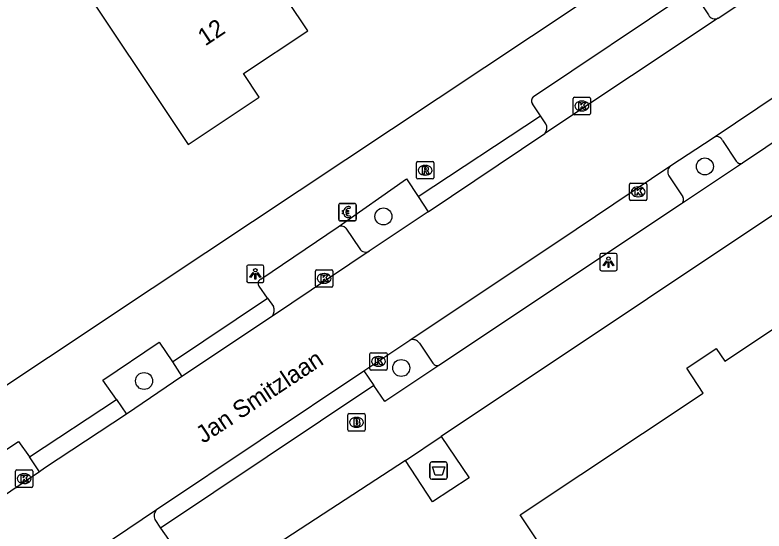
# Model space of a CAD drawing. Extents: x 161354 to 161876, y 382161 to 382804.
# Drawn here: x 161566.47 to 161609.6, y 382598.71 to 382628.43 of the extents above; entities that cross this region are included whole.
import ezdxf

# ---------------------------------------------------------------- set-up
doc = ezdxf.new("R2010")
doc.units = 0
for name, color, linetype in [('IMGEO_Afval_apart_plaats', 7, 'Continuous'), ('IMGEO_Betaalautomaat', 7, 'Continuous'), ('IMGEO_Boom', 7, 'Continuous'), ('IMGEO_Brandkraan', 7, 'Continuous'), ('IMGEO_Kolk', 7, 'Continuous'), ('IMGEO_Lichtpunt', 7, 'Continuous'), ('IMGEO_Openbare_ruimte_label', 7, 'Continuous'), ('IMGEO_Pand', 7, 'Continuous'), ('IMGEO_Pand_nummerreeks', 7, 'Continuous'), ('IMGEO_Parkeervlak_open', 7, 'Continuous'), ('IMGEO_Rijbaan_lokaal_open', 7, 'Continuous'), ('IMGEO_Rioolput', 7, 'Continuous'), ('IMGEO_Voetpad_gesloten', 7, 'Continuous'), ('IMGEO_Voetpad_open', 7, 'Continuous')]:
    doc.layers.add(name, color=color, linetype=linetype)

msp = doc.modelspace()

# ---------------------------------------------------------------- linework, layer by layer
at = {"layer": 'IMGEO_Afval_apart_plaats'}
for p, q in [((161590.37, 382601.787), (161590.37, 382602.587)), ((161590.37, 382602.587), (161590.37, 382601.787)), ((161590.47, 382602.687), (161591.26, 382602.687)), ((161591.26, 382602.687), (161590.47, 382602.687)), ((161591.36, 382602.587), (161591.36, 382601.787)), ((161591.36, 382601.787), (161591.36, 382602.587)), ((161591.26, 382601.687), (161590.47, 382601.687)), ((161590.47, 382601.687), (161591.26, 382601.687))]:
    msp.add_line(p, q, dxfattribs=at)
msp.add_lwpolyline([(161590.513, 382602.401), (161591.217, 382602.401), (161591.068, 382601.931), (161590.662, 382601.931), (161590.513, 382602.401)], dxfattribs=at)
for centre, start, end in [((161590.47, 382602.587), 90, 180), ((161590.47, 382602.587), 90, 180), ((161591.26, 382602.587), 0, 90), ((161591.26, 382602.587), 360, 90), ((161590.47, 382601.787), 180, 270), ((161590.47, 382601.787), 180, 270), ((161591.26, 382601.787), 270, 0), ((161591.26, 382601.787), 270, 0)]:
    msp.add_arc(centre, 0.1, start, end, dxfattribs=at)
at = {"layer": 'IMGEO_Betaalautomaat'}
for p, q in [((161585.189, 382617.577), (161586.03, 382617.577)), ((161586.03, 382617.577), (161585.189, 382617.577)), ((161585.114, 382616.653), (161585.114, 382617.494)), ((161585.114, 382617.494), (161585.114, 382616.653)), ((161585.397, 382617.041), (161585.397, 382617.109)), ((161585.518, 382617.109), (161585.518, 382617.041)), ((161585.776, 382617.382), (161585.759, 382617.282)), ((161586.113, 382617.503), (161586.113, 382616.662)), ((161586.113, 382616.662), (161586.113, 382617.503)), ((161585.763, 382616.876), (161585.785, 382616.789)), ((161586.039, 382616.578), (161585.198, 382616.578)), ((161585.198, 382616.578), (161586.039, 382616.578))]:
    msp.add_line(p, q, dxfattribs=at)
for points in [[(161585.397, 382617.109), (161585.328, 382617.109), (161585.328, 382617.178), (161585.407, 382617.178)], [(161585.529, 382617.178), (161585.676, 382617.178), (161585.676, 382617.109), (161585.518, 382617.109)], [(161585.402, 382616.972), (161585.328, 382616.972), (161585.328, 382617.041), (161585.397, 382617.041)], [(161585.518, 382617.041), (161585.676, 382617.041), (161585.676, 382616.972), (161585.532, 382616.972)]]:
    msp.add_lwpolyline(points, dxfattribs=at)
for centre, radius, start, end in [((161585.192, 382617.5), 0.0779, 92.4484, 184.2845), ((161585.192, 382617.5), 0.0779, 92.4484, 184.2845), ((161586.036, 382617.5), 0.0779, 2.4484, 94.2845), ((161586.036, 382617.5), 0.0779, 2.4484, 94.2845), ((161585.69, 382617.102), 0.293, 73.014, 165.0139), ((161585.696, 382617.115), 0.179, 69.3236, 159.5683), ((161585.192, 382616.656), 0.0779, 182.4484, 274.2845), ((161585.192, 382616.656), 0.0779, 182.4484, 274.2845), ((161585.663, 382617.027), 0.267, 191.8096, 297.0389), ((161585.696, 382617.042), 0.179, 202.7625, 291.8693), ((161586.036, 382616.656), 0.0779, 272.4484, 4.2845), ((161586.036, 382616.656), 0.0779, 272.4484, 4.2845)]:
    msp.add_arc(centre, radius, start, end, dxfattribs=at)
at = {"layer": 'IMGEO_Boom'}
for centre in [(161606.198, 382619.709), (161587.688, 382616.829), (161588.717, 382608.1), (161573.904, 382607.351)]:
    msp.add_circle(centre, 0.489, dxfattribs=at)
at = {"layer": 'IMGEO_Brandkraan'}
for p, q in [((161585.712, 382605.47), (161586.564, 382605.47)), ((161585.637, 382604.544), (161585.637, 382605.396)), ((161586.125, 382605.25), (161586.15, 382605.25)), ((161586.638, 382605.396), (161586.638, 382604.544)), ((161586.148, 382604.69), (161586.123, 382604.69)), ((161586.564, 382604.47), (161585.712, 382604.47))]:
    msp.add_line(p, q, dxfattribs=at)
for points in [[(161585.712, 382605.47), (161586.564, 382605.47)], [(161585.637, 382604.544), (161585.637, 382605.396)], [(161585.985, 382605.17), (161585.985, 382604.77), (161586.198, 382604.77)], [(161586.216, 382605.17), (161585.985, 382605.17)], [(161586.164, 382605.089), (161586.11, 382605.089), (161586.11, 382605.013)], [(161586.11, 382605.013), (161586.163, 382605.013)], [(161586.638, 382605.396), (161586.638, 382604.544)], [(161586.172, 382604.937), (161586.11, 382604.937), (161586.11, 382604.856)], [(161586.11, 382604.856), (161586.172, 382604.856)], [(161586.564, 382604.47), (161585.712, 382604.47)]]:
    msp.add_lwpolyline(points, dxfattribs=at)
for centre, radius, start, end in [((161585.714, 382605.394), 0.0765, 91.552, 178.448), ((161585.714, 382605.394), 0.0765, 91.552, 178.448), ((161586.562, 382605.394), 0.0765, 1.552, 88.448), ((161586.562, 382605.394), 0.0765, 1.552, 88.448), ((161586.165, 382605.051), 0.0379, 267.8285, 90.9355), ((161586.22, 382605.025), 0.145, 59.4692, 91.5367), ((161586.245, 382605.072), 0.0922, 285.5137, 58.1501), ((161586.173, 382604.896), 0.0404, 269.8759, 90.5077), ((161586.204, 382605.021), 0.251, 268.6676, 293.5347), ((161586.25, 382604.88), 0.105, 301.3115, 78.989), ((161585.714, 382604.546), 0.0765, 181.552, 268.448), ((161585.714, 382604.546), 0.0765, 181.552, 268.448), ((161586.562, 382604.546), 0.0765, 271.552, 358.448), ((161586.562, 382604.546), 0.0765, 271.552, 358.448)]:
    msp.add_arc(centre, radius, start, end, dxfattribs=at)
for centre, major_axis, ratio, start_param, end_param in [((161586.124, 382604.97), (-0.387, 0.002), 0.722429, 4.712389, 7.853982), ((161586.149, 382604.97), (-0.39, 0.002), 0.717154, 1.570796, 4.712389)]:
    msp.add_ellipse(centre, major_axis=major_axis, ratio=ratio, start_param=start_param, end_param=end_param, dxfattribs=at)
at = {"layer": 'IMGEO_Kolk'}
for p, q in [((161598.619, 382622.763), (161598.619, 382623.615)), ((161598.694, 382623.689), (161599.546, 382623.689)), ((161599.62, 382623.615), (161599.62, 382622.763)), ((161599.107, 382623.469), (161599.132, 382623.469)), ((161599.546, 382622.689), (161598.694, 382622.689)), ((161599.13, 382622.909), (161599.105, 382622.909)), ((161601.855, 382617.819), (161601.855, 382618.671)), ((161601.93, 382618.745), (161602.782, 382618.745)), ((161602.343, 382618.525), (161602.368, 382618.525)), ((161602.856, 382618.671), (161602.856, 382617.819)), ((161602.366, 382617.965), (161602.341, 382617.965)), ((161602.782, 382617.745), (161601.93, 382617.745)), ((161583.78, 382612.832), (161583.78, 382613.684)), ((161583.855, 382613.758), (161584.707, 382613.758)), ((161584.781, 382613.684), (161584.781, 382612.832)), ((161584.268, 382613.538), (161584.293, 382613.538)), ((161584.291, 382612.978), (161584.266, 382612.978)), ((161584.707, 382612.758), (161583.855, 382612.758)), ((161586.903, 382608.055), (161586.903, 382608.907)), ((161586.978, 382608.981), (161587.83, 382608.981)), ((161587.904, 382608.907), (161587.904, 382608.055)), ((161587.391, 382608.761), (161587.416, 382608.761)), ((161587.414, 382608.201), (161587.389, 382608.201)), ((161587.83, 382607.981), (161586.978, 382607.981)), ((161566.5, 382601.3), (161566.5, 382602.152)), ((161566.575, 382602.226), (161567.427, 382602.226)), ((161566.988, 382602.006), (161567.013, 382602.006)), ((161567.501, 382602.152), (161567.501, 382601.3)), ((161567.427, 382601.226), (161566.575, 382601.226)), ((161567.011, 382601.446), (161566.986, 382601.446))]:
    msp.add_line(p, q, dxfattribs=at)
for points in [[(161598.619, 382622.763), (161598.619, 382623.615)], [(161598.694, 382623.689), (161599.546, 382623.689)], [(161599.62, 382623.615), (161599.62, 382622.763)], [(161598.94, 382623.389), (161599.063, 382623.389), (161599.063, 382623.238), (161599.193, 382623.389), (161599.357, 382623.389), (161599.211, 382623.238), (161599.364, 382622.989), (161599.212, 382622.989), (161599.127, 382623.153), (161599.063, 382623.086), (161599.063, 382622.989), (161598.94, 382622.989), (161598.94, 382623.389)], [(161599.546, 382622.689), (161598.694, 382622.689)], [(161601.855, 382617.819), (161601.855, 382618.671)], [(161601.93, 382618.745), (161602.782, 382618.745)], [(161602.176, 382618.445), (161602.299, 382618.445), (161602.299, 382618.294), (161602.429, 382618.445), (161602.593, 382618.445), (161602.447, 382618.294), (161602.6, 382618.045), (161602.448, 382618.045), (161602.363, 382618.209), (161602.299, 382618.142), (161602.299, 382618.045), (161602.176, 382618.045), (161602.176, 382618.445)], [(161602.856, 382618.671), (161602.856, 382617.819)], [(161602.782, 382617.745), (161601.93, 382617.745)], [(161583.78, 382612.832), (161583.78, 382613.684)], [(161583.855, 382613.758), (161584.707, 382613.758)], [(161584.781, 382613.684), (161584.781, 382612.832)], [(161584.101, 382613.458), (161584.224, 382613.458), (161584.224, 382613.307), (161584.354, 382613.458), (161584.518, 382613.458), (161584.372, 382613.307), (161584.525, 382613.058), (161584.373, 382613.058), (161584.288, 382613.222), (161584.224, 382613.155), (161584.224, 382613.058), (161584.101, 382613.058), (161584.101, 382613.458)], [(161584.707, 382612.758), (161583.855, 382612.758)], [(161586.903, 382608.055), (161586.903, 382608.907)], [(161586.978, 382608.981), (161587.83, 382608.981)], [(161587.904, 382608.907), (161587.904, 382608.055)], [(161587.224, 382608.681), (161587.347, 382608.681), (161587.347, 382608.53), (161587.477, 382608.681), (161587.641, 382608.681), (161587.495, 382608.53), (161587.648, 382608.281), (161587.496, 382608.281), (161587.411, 382608.445), (161587.347, 382608.378), (161587.347, 382608.281), (161587.224, 382608.281), (161587.224, 382608.681)], [(161587.83, 382607.981), (161586.978, 382607.981)], [(161566.5, 382601.3), (161566.5, 382602.152)], [(161566.575, 382602.226), (161567.427, 382602.226)], [(161567.501, 382602.152), (161567.501, 382601.3)], [(161566.821, 382601.926), (161566.944, 382601.926), (161566.944, 382601.775), (161567.074, 382601.926), (161567.238, 382601.926), (161567.092, 382601.775), (161567.245, 382601.526), (161567.093, 382601.526), (161567.008, 382601.69), (161566.944, 382601.623), (161566.944, 382601.526), (161566.821, 382601.526), (161566.821, 382601.926)], [(161567.427, 382601.226), (161566.575, 382601.226)]]:
    msp.add_lwpolyline(points, dxfattribs=at)
for centre, start, end in [((161598.696, 382623.613), 91.552, 178.448), ((161598.696, 382623.613), 91.552, 178.448), ((161599.544, 382623.613), 1.552, 88.448), ((161599.544, 382623.613), 1.552, 88.448), ((161598.696, 382622.765), 181.552, 268.448), ((161598.696, 382622.765), 181.552, 268.448), ((161599.544, 382622.765), 271.552, 358.448), ((161599.544, 382622.765), 271.552, 358.448), ((161601.932, 382618.669), 91.552, 178.448), ((161601.932, 382618.669), 91.552, 178.448), ((161602.78, 382618.669), 1.552, 88.448), ((161602.78, 382618.669), 1.552, 88.448), ((161601.932, 382617.821), 181.552, 268.448), ((161601.932, 382617.821), 181.552, 268.448), ((161602.78, 382617.821), 271.552, 358.448), ((161602.78, 382617.821), 271.552, 358.448), ((161583.857, 382613.682), 91.552, 178.448), ((161583.857, 382613.682), 91.552, 178.448), ((161584.705, 382613.682), 1.552, 88.448), ((161584.705, 382613.682), 1.552, 88.448), ((161583.857, 382612.834), 181.552, 268.448), ((161583.857, 382612.834), 181.552, 268.448), ((161584.705, 382612.834), 271.552, 358.448), ((161584.705, 382612.834), 271.552, 358.448), ((161586.98, 382608.905), 91.552, 178.448), ((161586.98, 382608.905), 91.552, 178.448), ((161587.828, 382608.905), 1.552, 88.448), ((161587.828, 382608.905), 1.552, 88.448), ((161586.98, 382608.057), 181.552, 268.448), ((161586.98, 382608.057), 181.552, 268.448), ((161587.828, 382608.057), 271.552, 358.448), ((161587.828, 382608.057), 271.552, 358.448), ((161566.577, 382602.15), 91.552, 178.448), ((161566.577, 382602.15), 91.552, 178.448), ((161567.425, 382602.15), 1.552, 88.448), ((161567.425, 382602.15), 1.552, 88.448), ((161566.577, 382601.302), 181.552, 268.448), ((161566.577, 382601.302), 181.552, 268.448), ((161567.425, 382601.302), 271.552, 358.448), ((161567.425, 382601.302), 271.552, 358.448)]:
    msp.add_arc(centre, 0.0765, start, end, dxfattribs=at)
for centre, major_axis, ratio, start_param, end_param in [((161599.106, 382623.189), (-0.387, 0.002), 0.722429, 4.712389, 7.853982), ((161599.131, 382623.189), (-0.39, 0.002), 0.717154, 1.570796, 4.712389), ((161602.342, 382618.245), (-0.387, 0.002), 0.722429, 4.712389, 7.853982), ((161602.367, 382618.245), (-0.39, 0.002), 0.717154, 1.570796, 4.712389), ((161584.267, 382613.258), (-0.387, 0.002), 0.722429, 4.712389, 7.853982), ((161584.292, 382613.258), (-0.39, 0.002), 0.717154, 1.570796, 4.712389), ((161587.39, 382608.481), (-0.387, 0.002), 0.722429, 4.712389, 7.853982), ((161587.415, 382608.481), (-0.39, 0.002), 0.717154, 1.570796, 4.712389), ((161566.987, 382601.726), (-0.387, 0.002), 0.722429, 4.712389, 7.853982), ((161567.012, 382601.726), (-0.39, 0.002), 0.717154, 1.570796, 4.712389)]:
    msp.add_ellipse(centre, major_axis=major_axis, ratio=ratio, start_param=start_param, end_param=end_param, dxfattribs=at)
at = {"layer": 'IMGEO_Lichtpunt'}
for p, q in [((161600.151, 382614.603), (161600.151, 382613.796)), ((161600.151, 382614.603), (161600.151, 382613.796)), ((161601.053, 382614.698), (161600.245, 382614.698)), ((161601.053, 382614.698), (161600.245, 382614.698)), ((161601.147, 382613.796), (161601.147, 382614.603)), ((161601.147, 382613.796), (161601.147, 382614.603)), ((161579.814, 382613.93), (161579.814, 382613.123)), ((161579.814, 382613.93), (161579.814, 382613.123)), ((161580.716, 382614.025), (161579.908, 382614.025)), ((161580.716, 382614.025), (161579.908, 382614.025)), ((161580.81, 382613.123), (161580.81, 382613.93)), ((161580.81, 382613.123), (161580.81, 382613.93)), ((161600.245, 382613.702), (161601.053, 382613.702)), ((161600.245, 382613.702), (161601.053, 382613.702)), ((161579.908, 382613.029), (161580.716, 382613.029)), ((161579.908, 382613.029), (161580.716, 382613.029))]:
    msp.add_line(p, q, dxfattribs=at)
for points in [[(161600.525, 382614.267), (161600.564, 382614.239), (161600.376, 382613.977), (161600.338, 382614.004), (161600.525, 382614.267)], [(161600.627, 382614.219), (161600.674, 382614.219), (161600.674, 382613.897), (161600.627, 382613.897), (161600.627, 382614.219)], [(161600.737, 382614.239), (161600.775, 382614.266), (161600.962, 382614.004), (161600.923, 382613.976), (161600.737, 382614.239)], [(161580.188, 382613.594), (161580.227, 382613.566), (161580.039, 382613.304), (161580.001, 382613.331), (161580.188, 382613.594)], [(161580.29, 382613.546), (161580.337, 382613.546), (161580.337, 382613.224), (161580.29, 382613.224), (161580.29, 382613.546)], [(161580.4, 382613.566), (161580.438, 382613.593), (161580.625, 382613.331), (161580.586, 382613.303), (161580.4, 382613.566)]]:
    msp.add_lwpolyline(points, dxfattribs=at)
for centre in [(161600.65, 382614.401), (161580.313, 382613.728)]:
    msp.add_circle(centre, 0.0994, dxfattribs=at)
for centre, start, end in [((161600.245, 382614.603), 90, 180), ((161600.245, 382614.603), 90, 180), ((161601.053, 382614.603), 0, 90), ((161601.053, 382614.603), 0, 90), ((161579.908, 382613.93), 90, 180), ((161579.908, 382613.93), 90, 180), ((161580.716, 382613.93), 0, 90), ((161580.716, 382613.93), 0, 90), ((161600.245, 382613.796), 180, 270), ((161600.245, 382613.796), 180, 270), ((161601.053, 382613.796), 270, 0), ((161601.053, 382613.796), 270, 360), ((161579.908, 382613.123), 180, 270), ((161579.908, 382613.123), 180, 270), ((161580.716, 382613.123), 270, 0), ((161580.716, 382613.123), 270, 360)]:
    msp.add_arc(centre, 0.0946, start, end, dxfattribs=at)
at = {"layer": 'IMGEO_Pand'}
for points in [[(161565.599, 382634.459), (161568.37, 382630.297), (161569.66, 382631.156), (161576.439, 382620.977), (161580.533, 382623.704), (161579.633, 382625.056), (161583.334, 382627.521), (161580.992, 382631.038), (161582.16, 382631.816), (161579.388, 382635.978), (161576.632, 382640.114), (161575.975, 382639.677), (161575.266, 382640.743), (161575.924, 382641.181), (161573.679, 382644.552), (161575.985, 382646.088), (161572.304, 382651.615), (161565.14, 382646.843), (161570.96, 382638.104), (161569.803, 382637.333), (161569.021, 382638.506), (161566.041, 382636.521), (161566.822, 382635.347), (161565.599, 382634.459)], [(161609.323, 382577.814), (161601.467, 382589.619), (161598.697, 382593.782), (161599.229, 382594.136), (161595.569, 382599.636), (161606.108, 382606.65), (161605.154, 382608.083), (161606.858, 382609.217), (161607.344, 382608.485), (161625.993, 382620.895)]]:
    msp.add_lwpolyline(points, dxfattribs=at)
at = {"layer": 'IMGEO_Parkeervlak_open'}
for points in [[(161605.625, 382629.631), (161606.407, 382628.432)], [(161607.212, 382621.21), (161608.007, 382620.009)], [(161604.13, 382619.174), (161604.931, 382617.96)], [(161585.528, 382616.145), (161586.327, 382614.968)], [(161589.758, 382609.534), (161590.54, 382608.383)]]:
    msp.add_lwpolyline(points, dxfattribs=at)
for centre, radius, start, end in [((161606.767, 382628.608), 0.401, 205.9885, 298.6427), ((161606.878, 382621.057), 0.368, 24.6315, 123.0538), ((161604.529, 382619.407), 0.462, 129.6828, 210.2901), ((161608.241, 382620.144), 0.27, 210.0365, 297.6516), ((161604.653, 382617.795), 0.323, 309.9997, 30.7608), ((161585.25, 382615.898), 0.371, 41.6099, 117.1043), ((161586.677, 382615.189), 0.414, 212.2674, 298.9748), ((161589.39, 382609.291), 0.441, 33.4839, 113.1759), ((161590.789, 382608.525), 0.287, 209.7009, 300.5265)]:
    msp.add_arc(centre, radius, start, end, dxfattribs=at)
at = {"layer": 'IMGEO_Rijbaan_lokaal_open'}
for points in [[(161606.959, 382628.256), (161609.534, 382629.982)], [(161606.677, 382621.365), (161617.031, 382628.308)], [(161606.959, 382628.256), (161596.988, 382621.601)], [(161590.272, 382617.093), (161596.988, 382621.601)], [(161604.234, 382619.763), (161606.677, 382621.365)], [(161589.217, 382609.696), (161598.787, 382616.092), (161604.234, 382619.763)], [(161590.272, 382617.093), (161586.877, 382614.827)], [(161586.877, 382614.827), (161581.294, 382611.082)], [(161581.294, 382611.082), (161576.086, 382607.606)], [(161586.553, 382607.94), (161589.217, 382609.696)], [(161576.086, 382607.606), (161572.895, 382605.439)], [(161574.626, 382599.941), (161586.553, 382607.94)], [(161572.895, 382605.439), (161568.174, 382602.328), (161567.876, 382602.127)], [(161567.876, 382602.127), (161562.92, 382598.78)], [(161568.848, 382596.061), (161574.626, 382599.941)]]:
    msp.add_lwpolyline(points, dxfattribs=at)
at = {"layer": 'IMGEO_Rioolput'}
for p, q in [((161589.592, 382619.06), (161589.592, 382619.912)), ((161589.667, 382619.986), (161590.519, 382619.986)), ((161590.08, 382619.766), (161590.105, 382619.766)), ((161590.593, 382619.912), (161590.593, 382619.06)), ((161590.519, 382618.986), (161589.667, 382618.986)), ((161590.103, 382619.206), (161590.078, 382619.206))]:
    msp.add_line(p, q, dxfattribs=at)
for points in [[(161589.592, 382619.06), (161589.592, 382619.912)], [(161589.667, 382619.986), (161590.519, 382619.986)], [(161590.181, 382619.684), (161589.929, 382619.686), (161589.929, 382619.286)], [(161590.593, 382619.912), (161590.593, 382619.06)], [(161589.929, 382619.286), (161590.053, 382619.286), (161590.053, 382619.448), (161590.064, 382619.448)], [(161590.107, 382619.605), (161590.053, 382619.605), (161590.053, 382619.524)], [(161590.053, 382619.524), (161590.105, 382619.524)], [(161590.111, 382619.419), (161590.182, 382619.286), (161590.322, 382619.286), (161590.257, 382619.412)], [(161590.519, 382618.986), (161589.667, 382618.986)]]:
    msp.add_lwpolyline(points, dxfattribs=at)
for centre, radius, start, end in [((161589.669, 382619.91), 0.0765, 91.552, 178.448), ((161589.669, 382619.91), 0.0765, 91.552, 178.448), ((161590.18, 382619.574), 0.109, 350.3612, 89.416), ((161590.517, 382619.91), 0.0765, 1.552, 88.448), ((161590.517, 382619.91), 0.0765, 1.552, 88.448), ((161590.063, 382619.395), 0.0533, 26.0293, 88.6989), ((161590.089, 382619.713), 0.19, 274.7715, 282.9687), ((161590.113, 382619.509), 0.0964, 77.0061, 93.1865), ((161590.127, 382619.566), 0.0378, 276.6634, 79.6772), ((161590.178, 382619.574), 0.112, 277.5842, 350.9817), ((161590.162, 382619.359), 0.108, 29.5134, 73.7905), ((161589.669, 382619.062), 0.0765, 181.552, 268.448), ((161589.669, 382619.062), 0.0765, 181.552, 268.448), ((161590.517, 382619.062), 0.0765, 271.552, 358.448), ((161590.517, 382619.062), 0.0765, 271.552, 358.448)]:
    msp.add_arc(centre, radius, start, end, dxfattribs=at)
for centre, major_axis, ratio, start_param, end_param in [((161590.079, 382619.486), (-0.387, 0.002), 0.722429, 4.712389, 7.853982), ((161590.104, 382619.486), (-0.39, 0.002), 0.717154, 1.570796, 4.712389)]:
    msp.add_ellipse(centre, major_axis=major_axis, ratio=ratio, start_param=start_param, end_param=end_param, dxfattribs=at)
at = {"layer": 'IMGEO_Voetpad_gesloten'}
for points in [[(161591.014, 382604.147), (161592.626, 382601.772), (161590.519, 382600.398), (161588.954, 382602.772)], [(161588.954, 382602.772), (161591.014, 382604.147)]]:
    msp.add_lwpolyline(points, dxfattribs=at)
at = {"layer": 'IMGEO_Voetpad_open'}
for points in [[(161628.452, 382648.518), (161612.356, 382637.679), (161612.276, 382637.879), (161577.471, 382614.736), (161574.373, 382612.676), (161556.508, 382600.797), (161530.719, 382583.477), (161519.986, 382585.99)], [(161642.272, 382638.554), (161626.724, 382627.988), (161591.014, 382604.147)], [(161596.327, 382623.729), (161605.214, 382629.699)], [(161617.655, 382626.128), (161608.366, 382619.905)], [(161596.732, 382622.631), (161596.273, 382623.316)], [(161589.689, 382617.973), (161596.732, 382622.631)], [(161597.04, 382622.17), (161596.732, 382622.631)], [(161608.366, 382619.905), (161604.861, 382617.547)], [(161585.081, 382616.229), (161589.012, 382618.995), (161589.689, 382617.973)], [(161589.689, 382617.973), (161590.272, 382617.093)], [(161604.861, 382617.547), (161590.935, 382608.278)], [(161580.638, 382613.21), (161585.081, 382616.229)], [(161581.017, 382612.127), (161580.541, 382612.811)], [(161575.54, 382608.454), (161581.017, 382612.127)], [(161581.017, 382612.127), (161581.354, 382611.643)], [(161572.313, 382606.29), (161571.539, 382607.403), (161574.77, 382609.585), (161575.54, 382608.454)], [(161575.54, 382608.454), (161576.086, 382607.606)], [(161590.935, 382608.278), (161587.772, 382606.172), (161587.144, 382607.09)], [(161586.553, 382607.94), (161587.144, 382607.09)], [(161587.144, 382607.09), (161574.859, 382598.875)], [(161567.302, 382602.987), (161572.313, 382606.29)], [(161572.313, 382606.29), (161572.895, 382605.439)], [(161562.64, 382599.822), (161562.017, 382600.769), (161566.681, 382603.875), (161567.302, 382602.987)], [(161567.876, 382602.127), (161567.302, 382602.987)], [(161588.954, 382602.772), (161572.092, 382591.77), (161539.981, 382570.178), (161537.341, 382557.85)], [(161574.524, 382599.371), (161574.859, 382598.875)], [(161574.859, 382598.875), (161575.536, 382597.897), (161570.33, 382594.467)]]:
    msp.add_lwpolyline(points, dxfattribs=at)
for centre, radius, start, end in [((161596.505, 382623.496), 0.293, 127.3152, 217.7864), ((161596.609, 382621.922), 0.497, 319.6602, 29.8964), ((161580.706, 382612.982), 0.238, 106.6632, 226.0088), ((161580.859, 382611.412), 0.546, 322.8092, 24.9815), ((161575.002, 382599.58), 0.522, 136.142, 203.5669)]:
    msp.add_arc(centre, radius, start, end, dxfattribs=at)

# ---------------------------------------------------------------- texts
at = {"layer": 'IMGEO_Openbare_ruimte_label'}
msp.add_text('Jan Smitzlaan', height=1, rotation=33.4994, dxfattribs=at).set_placement((161577.316, 382603.725))
at = {"layer": 'IMGEO_Pand_nummerreeks'}
msp.add_text('12', height=1, rotation=33.6651, dxfattribs=at).set_placement((161577.425, 382626.613))

doc.saveas('drawing.dxf')
